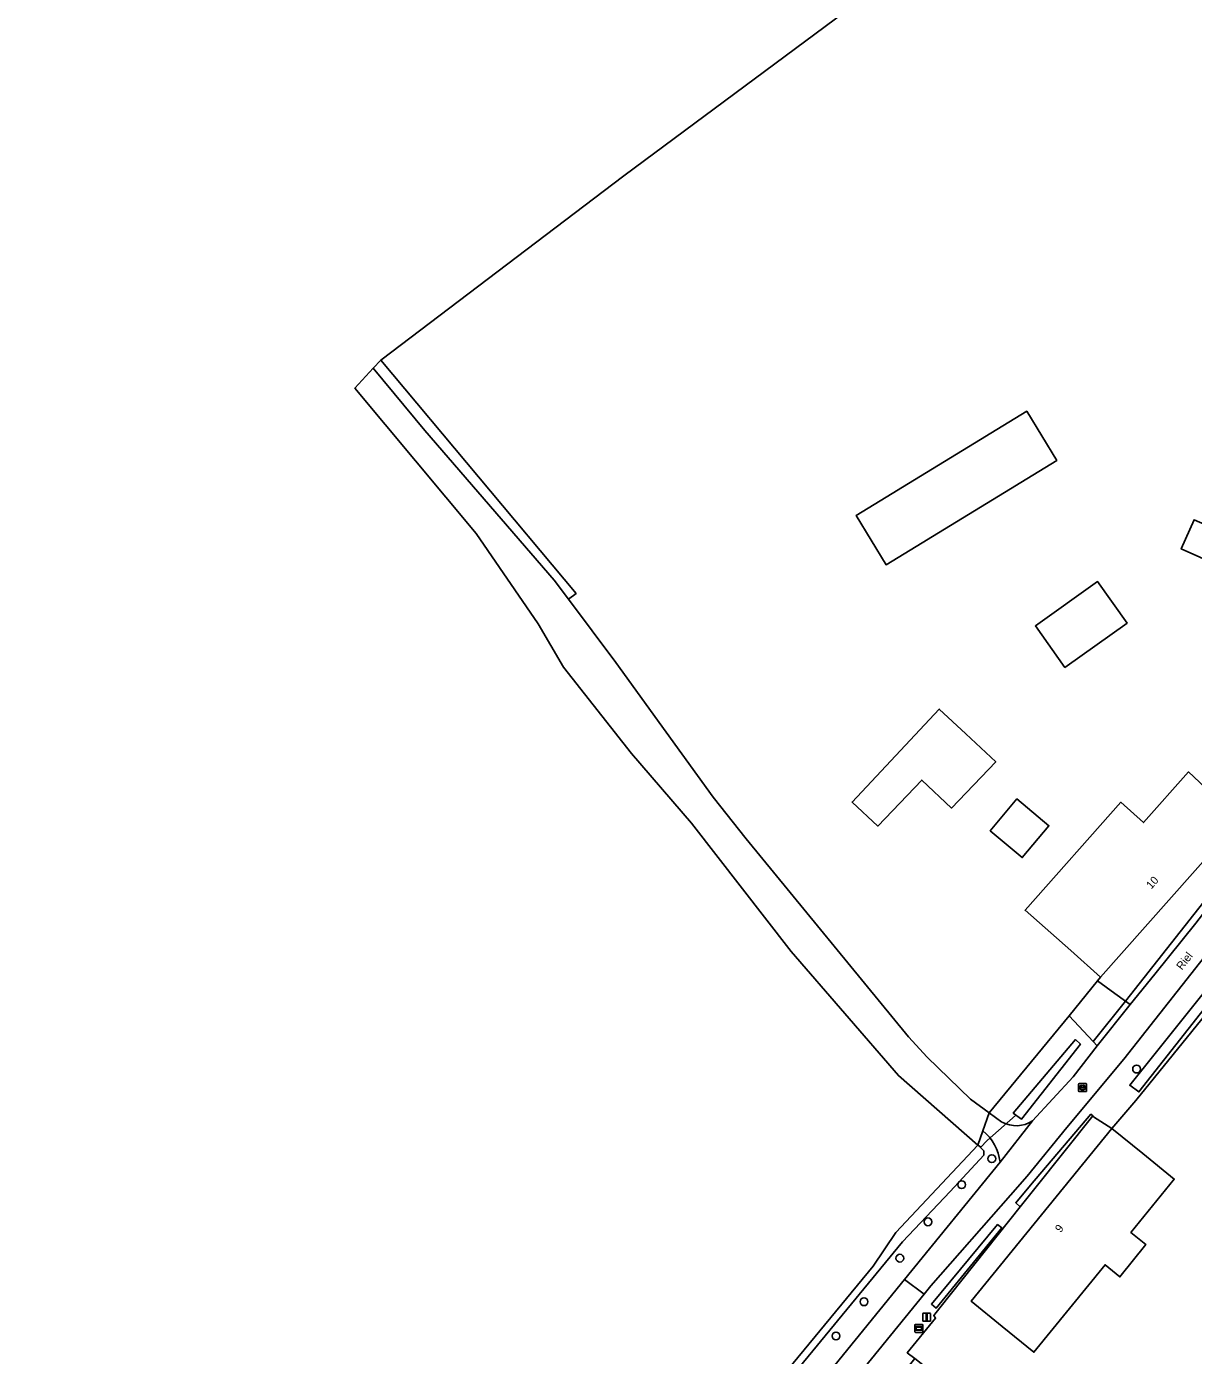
# Model space of a CAD drawing. Extents: x 163859 to 164644, y 379566 to 382155.
# Drawn here: x 164243.3 to 164389, y 381172.1 to 381338.2 of the extents above; entities that cross this region are included whole.
import ezdxf

# ---------------------------------------------------------------- set-up
doc = ezdxf.new("R2010")
doc.units = 0
for name, color, linetype in [('IMGEO_Boom', 7, 'Continuous'), ('IMGEO_Bouwland', 7, 'Continuous'), ('IMGEO_Duiker', 7, 'Continuous'), ('IMGEO_Erf', 7, 'Continuous'), ('IMGEO_Grasland_overig', 7, 'Continuous'), ('IMGEO_Groenvoorziening', 7, 'Continuous'), ('IMGEO_Hek', 7, 'Continuous'), ('IMGEO_Lichtmast', 7, 'Continuous'), ('IMGEO_Openbare_ruimte_label', 7, 'Continuous'), ('IMGEO_Pand', 7, 'Continuous'), ('IMGEO_Pand_nummerreeks', 7, 'Continuous'), ('IMGEO_Pand_overbouw', 7, 'Continuous'), ('IMGEO_Rijbaan_lokaal_gesloten', 7, 'Continuous'), ('IMGEO_Rijbaan_lokaal_halfverhard', 7, 'Continuous'), ('IMGEO_Rioolput', 7, 'Continuous'), ('IMGEO_Verklikker', 7, 'Continuous'), ('IMGEO_Voetpad_gesloten', 7, 'Continuous'), ('IMGEO_Voetpad_open', 7, 'Continuous'), ('IMGEO_Waterloop', 7, 'Continuous')]:
    doc.layers.add(name, color=color, linetype=linetype)

msp = doc.modelspace()

# ---------------------------------------------------------------- linework, layer by layer
at = {"layer": 'IMGEO_Boom'}
for centre in [(164381.95, 381207.91), (164363.86, 381196.71), (164360.09, 381193.46), (164355.88, 381188.82), (164352.37, 381184.28), (164347.89, 381178.84), (164344.39, 381174.56)]:
    msp.add_circle(centre, 0.489, dxfattribs=at)
at = {"layer": 'IMGEO_Bouwland'}
msp.add_lwpolyline([(164187.9, 381189.23), (164278.22, 381095.19), (164281.5, 381099.85), (164286.83, 381106.67), (164289.04, 381110.56), (164349.03, 381183.28), (164351.85, 381187.47), (164362.1, 381198.39), (164352.18, 381207.09), (164338.77, 381222.6), (164326.32, 381238.65), (164318.83, 381247.33), (164310.33, 381258.14), (164307.18, 381263.52), (164299.42, 381274.81), (164284.28, 381292.99), (164286.58, 381295.47), (164287.52, 381296.47), (164317.88, 381319.5), (164350.6, 381343.85)], dxfattribs=at)
at = {"layer": 'IMGEO_Duiker'}
msp.add_lwpolyline([(164362.45, 381198.09), (164363.27, 381198.97), (164366.81, 381202.09)], dxfattribs=at)
at = {"layer": 'IMGEO_Erf'}
msp.add_lwpolyline([(164350.6, 381343.85), (164317.88, 381319.5), (164287.52, 381296.47), (164311.91, 381267.33), (164310.95, 381266.61), (164316.87, 381258.7), (164323.16, 381250), (164329.04, 381241.88), (164333.15, 381236.67), (164353.46, 381211.92), (164355.77, 381209.41), (164361.21, 381204.13), (164363.54, 381202.45), (164373.51, 381214.58), (164377.08, 381218.93), (164377.46, 381219.39), (164373.72, 381222.71), (164368.02, 381227.76), (164379.96, 381241.24), (164382.83, 381238.7), (164388.45, 381245.03), (164391.21, 381242.44)], dxfattribs=at)
for points in [[(164350.64, 381270.92), (164346.89, 381277.06), (164368.23, 381290.1), (164371.98, 381283.96)], [(164377.07, 381268.82), (164380.77, 381263.63), (164373, 381258.09), (164369.3, 381263.28)], [(164360.62, 381249.78), (164364.35, 381246.28), (164358.84, 381240.52), (164355.11, 381244.02), (164349.6, 381238.26), (164346.39, 381241.26), (164357.3, 381252.89)], [(164370.99, 381238.31), (164367.66, 381234.34), (164363.67, 381237.69), (164367, 381241.66)], [(164458.6, 381206.61), (164452.32, 381209.05), (164442.73, 381196.98), (164413.91, 381220.59), (164411.58, 381223.53), (164405.79, 381228.47), (164403.37, 381230.53), (164381.86, 381203.99), (164378.85, 381200.5), (164376.58, 381201.96), (164376.48, 381202.06), (164369.24, 381192.97), (164367.41, 381190.7), (164357.36, 381178.07), (164356.6, 381177.11), (164356.84, 381176.79), (164353.3, 381172.46), (164354.22, 381171.73), (164404.86, 381131.61), (164431.84, 381169.01), (164446.23, 381186.49), (164447.34, 381188.47), (164448.06, 381190.36)], [(164378.85, 381200.5), (164382.73, 381197.35), (164386.65, 381194.16), (164381.23, 381187.51), (164383.12, 381185.97), (164379.86, 381181.95), (164378.01, 381183.46), (164369.12, 381172.53), (164365.17, 381175.74), (164361.29, 381178.9)]]:
    msp.add_lwpolyline(points, close=True, dxfattribs=at)
at = {"layer": 'IMGEO_Grasland_overig'}
for points in [[(164287.52, 381296.47), (164286.58, 381295.47), (164293.02, 381287.69), (164309.18, 381268.98), (164310.95, 381266.61), (164311.91, 381267.33)], [(164286.58, 381295.47), (164284.28, 381292.99), (164299.42, 381274.81), (164307.18, 381263.52), (164310.33, 381258.14), (164318.83, 381247.33), (164326.32, 381238.65), (164338.77, 381222.6), (164352.18, 381207.09), (164362.1, 381198.39), (164362.74, 381200.21), (164363.54, 381202.45), (164361.21, 381204.13), (164355.77, 381209.41), (164353.46, 381211.92), (164333.15, 381236.67), (164329.04, 381241.88), (164323.16, 381250), (164316.87, 381258.7), (164310.95, 381266.61), (164309.18, 381268.98), (164293.02, 381287.69)], [(164366.54, 381202.41), (164374.33, 381211.6), (164374.92, 381211.01), (164367.57, 381201.67)]]:
    msp.add_lwpolyline(points, close=True, dxfattribs=at)
for points in [[(164411.34, 381270.45), (164410.69, 381270.73), (164407.78, 381264.26), (164397.4, 381243.03), (164394.86, 381239.02), (164377.46, 381219.39), (164377.08, 381218.93), (164379.21, 381217.37), (164380.55, 381216.38), (164396.56, 381236.69), (164397.1, 381236.21), (164401.21, 381241.55), (164406.39, 381250), (164407.38, 381251.61)], [(164368.94, 381201.43), (164374.03, 381206.95), (164377.04, 381210.81), (164376.54, 381211.34), (164373.51, 381214.58), (164363.54, 381202.45), (164365.13, 381201.29)]]:
    msp.add_lwpolyline(points, dxfattribs=at)
msp.add_arc((164366.92, 381204.52), 3.69, 241.068, 303.2332, dxfattribs=at)
at = {"layer": 'IMGEO_Groenvoorziening'}
for points in [[(164431.96, 381299.66), (164429.94, 381295.69), (164428.15, 381292.04), (164426.2, 381287.59), (164423.08, 381279.48), (164417.3, 381265.29), (164413.63, 381256.97), (164407.49, 381245.09), (164401.6, 381236.08), (164380.37, 381209.13), (164373.24, 381200.61), (164368.28, 381194.51), (164366.18, 381192.15), (164356.26, 381180.83), (164355.42, 381179.8), (164327.62, 381145.68), (164299.26, 381110.37), (164285.34, 381092.57), (164271.16, 381074.14), (164257.14, 381055.39), (164248.19, 381042.64), (164246.03, 381039.89)], [(164351.1, 381167.85), (164354.22, 381171.73), (164353.3, 381172.46), (164356.84, 381176.79), (164356.6, 381177.11), (164357.36, 381178.07), (164367.41, 381190.7), (164366.86, 381191.21), (164368.7, 381193.39), (164376.24, 381202.26), (164376.48, 381202.06), (164376.58, 381201.96), (164378.85, 381200.5), (164381.86, 381203.99), (164403.37, 381230.53), (164409.33, 381239.2), (164409.26, 381239.26)], [(164362.74, 381200.21), (164362.1, 381198.39), (164362.45, 381198.19), (164362.45, 381198.09), (164362.88, 381197.68), (164362.88, 381197.17), (164358.66, 381192.61), (164352.68, 381186.34), (164315.21, 381140.78), (164290.33, 381110.01), (164284.87, 381100.39), (164279.89, 381093.78), (164279.12, 381094.43), (164278.22, 381095.19), (164276.13, 381091.25), (164277.51, 381089.86), (164260.42, 381068.3), (164239.55, 381038.87), (164238.07, 381040.68), (164237.86, 381040.39), (164240.37, 381037.27)], [(164325.21, 381147.51), (164352.96, 381181.62), (164364.89, 381196.29)]]:
    msp.add_lwpolyline(points, dxfattribs=at)
for points in [[(164381.09, 381205.89), (164402.81, 381233.02), (164403.79, 381232.48), (164382.23, 381205.05)], [(164356.32, 381178.54), (164364.57, 381188.47), (164365.11, 381188.09), (164356.92, 381178.05)]]:
    msp.add_lwpolyline(points, close=True, dxfattribs=at)
msp.add_arc((164358.9, 381195.56), 6.03, 6.9415, 50.4634, dxfattribs=at)
at = {"layer": 'IMGEO_Hek'}
msp.add_lwpolyline([(164387.17, 381367.35), (164350.6, 381343.85), (164317.88, 381319.5), (164287.52, 381296.47), (164311.91, 381267.33)], dxfattribs=at)
at = {"layer": 'IMGEO_Lichtmast'}
for p, q in [((164355.22, 381176.5), (164355.22, 381177.3)), ((164355.22, 381177.3), (164355.22, 381176.5)), ((164355.32, 381177.4), (164356.11, 381177.4)), ((164356.11, 381177.4), (164355.32, 381177.4)), ((164356.11, 381176.4), (164355.32, 381176.4)), ((164355.32, 381176.4), (164356.11, 381176.4)), ((164356.21, 381177.3), (164356.21, 381176.5)), ((164356.21, 381176.5), (164356.21, 381177.3))]:
    msp.add_line(p, q, dxfattribs=at)
msp.add_lwpolyline([(164355.64, 381177.28), (164355.79, 381177.28), (164355.79, 381176.53), (164355.64, 381176.53), (164355.64, 381177.28)], dxfattribs=at)
for centre, start, end in [((164355.32, 381177.3), 90, 180), ((164355.32, 381177.3), 90, 180), ((164355.32, 381176.5), 180, 270), ((164355.32, 381176.5), 180, 270), ((164356.11, 381177.3), 0, 90), ((164356.11, 381177.3), 360, 90), ((164356.11, 381176.5), 270, 0), ((164356.11, 381176.5), 270, 0)]:
    msp.add_arc(centre, 0.1, start, end, dxfattribs=at)
at = {"layer": 'IMGEO_Pand'}
for points in [[(164346.89, 381277.06), (164350.64, 381270.92), (164371.98, 381283.96), (164368.23, 381290.1)], [(164369.3, 381263.28), (164373, 381258.09), (164380.77, 381263.63), (164377.07, 381268.82)], [(164346.39, 381241.26), (164349.6, 381238.26), (164355.11, 381244.02), (164358.84, 381240.52), (164364.35, 381246.28), (164360.62, 381249.78), (164357.3, 381252.89)], [(164377.46, 381219.39), (164394.86, 381239.02), (164391.21, 381242.44), (164388.45, 381245.03), (164382.83, 381238.7), (164379.96, 381241.24), (164368.02, 381227.76), (164373.72, 381222.71)], [(164363.67, 381237.69), (164367.66, 381234.34), (164370.99, 381238.31), (164367, 381241.66)], [(164383.12, 381185.97), (164381.23, 381187.51), (164386.65, 381194.16), (164382.73, 381197.35), (164378.85, 381200.5), (164361.29, 381178.9), (164365.17, 381175.74), (164369.12, 381172.53), (164378.01, 381183.46), (164379.86, 381181.95)]]:
    msp.add_lwpolyline(points, close=True, dxfattribs=at)
at = {"layer": 'IMGEO_Pand_overbouw'}
msp.add_lwpolyline([(164393.81, 381274.5), (164389.13, 381276.55), (164387.52, 381272.89), (164392.2, 381270.84)], close=True, dxfattribs=at)
at = {"layer": 'IMGEO_Rijbaan_lokaal_gesloten'}
for points in [[(164389.34, 381226.14), (164384.21, 381219.76), (164381.13, 381215.96), (164377.04, 381210.81), (164374.03, 381206.95), (164368.94, 381201.43), (164364.89, 381196.29), (164352.96, 381181.62), (164355.42, 381179.8), (164356.26, 381180.83), (164366.18, 381192.15), (164368.28, 381194.51), (164373.24, 381200.61), (164380.37, 381209.13), (164401.6, 381236.08)], [(164271.16, 381074.14), (164285.34, 381092.57), (164299.26, 381110.37), (164327.62, 381145.68), (164355.42, 381179.8), (164352.96, 381181.62), (164325.21, 381147.51), (164297.15, 381112.5), (164283.09, 381094.56), (164268.85, 381076.08), (164254.82, 381057.26), (164245.63, 381044.28)]]:
    msp.add_lwpolyline(points, dxfattribs=at)
at = {"layer": 'IMGEO_Rijbaan_lokaal_halfverhard'}
for points in [[(164365.13, 381201.29), (164363.54, 381202.45), (164362.74, 381200.21)], [(164364.89, 381196.29), (164368.94, 381201.43)]]:
    msp.add_lwpolyline(points, dxfattribs=at)
for centre, radius, start, end in [((164366.92, 381204.52), 3.69, 241.068, 303.2332), ((164358.9, 381195.56), 6.03, 6.9415, 50.4634)]:
    msp.add_arc(centre, radius, start, end, dxfattribs=at)
at = {"layer": 'IMGEO_Rioolput'}
for p, q in [((164374.69, 381205.18), (164374.69, 381206.03)), ((164374.77, 381206.1), (164375.62, 381206.1)), ((164375.62, 381205.1), (164374.77, 381205.1)), ((164374.95, 381205.6), (164374.95, 381205.61)), ((164375.39, 381205.56), (164374.99, 381205.56)), ((164375, 381205.65), (164375.39, 381205.65)), ((164375.18, 381205.88), (164375.21, 381205.88)), ((164375.2, 381205.32), (164375.18, 381205.32)), ((164375.44, 381205.61), (164375.44, 381205.6)), ((164375.7, 381206.03), (164375.7, 381205.18))]:
    msp.add_line(p, q, dxfattribs=at)
for points in [[(164374.69, 381205.18), (164374.69, 381206.03)], [(164374.77, 381206.1), (164375.62, 381206.1)], [(164375.62, 381205.1), (164374.77, 381205.1)], [(164375.7, 381206.03), (164375.7, 381205.18)]]:
    msp.add_lwpolyline(points, dxfattribs=at)
for centre, radius, start, end in [((164374.77, 381206.03), 0.0765, 91.552, 178.448), ((164374.77, 381206.03), 0.0765, 91.552, 178.448), ((164374.77, 381205.18), 0.0765, 181.552, 268.448), ((164374.77, 381205.18), 0.0765, 181.552, 268.448), ((164374.99, 381205.61), 0.0403, 85.8775, 175.7526), ((164374.99, 381205.6), 0.0366, 178.938, 274.7102), ((164375.4, 381205.61), 0.0386, 1.7309, 96.639), ((164375.39, 381205.6), 0.043, 264.8664, 352.4533), ((164375.62, 381206.03), 0.0765, 1.552, 88.448), ((164375.62, 381206.03), 0.0765, 1.552, 88.448), ((164375.62, 381205.18), 0.0765, 271.552, 358.448), ((164375.62, 381205.18), 0.0765, 271.552, 358.448)]:
    msp.add_arc(centre, radius, start, end, dxfattribs=at)
for centre, major_axis, ratio, start_param, end_param in [((164375.18, 381205.6), (-0.387, 0.002), 0.722429, 4.712389, 7.853982), ((164375.21, 381205.6), (-0.39, 0.002), 0.717154, 1.570796, 4.712389)]:
    msp.add_ellipse(centre, major_axis=major_axis, ratio=ratio, start_param=start_param, end_param=end_param, dxfattribs=at)
at = {"layer": 'IMGEO_Verklikker'}
for p, q in [((164354.24, 381175.11), (164354.24, 381175.91)), ((164354.24, 381175.91), (164354.24, 381175.11)), ((164354.34, 381176.01), (164355.13, 381176.01)), ((164355.13, 381176.01), (164354.34, 381176.01)), ((164355.13, 381175.01), (164354.34, 381175.01)), ((164354.34, 381175.01), (164355.13, 381175.01)), ((164355.23, 381175.91), (164355.23, 381175.11)), ((164355.23, 381175.11), (164355.23, 381175.91))]:
    msp.add_line(p, q, dxfattribs=at)
for points in [[(164354.34, 381175.74), (164355.13, 381175.74), (164355.13, 381175.28), (164354.34, 381175.28), (164354.34, 381175.74)], [(164354.41, 381175.68), (164354.41, 381175.34), (164355.06, 381175.34), (164355.06, 381175.68), (164354.41, 381175.68)]]:
    msp.add_lwpolyline(points, dxfattribs=at)
for centre, start, end in [((164354.34, 381175.91), 90, 180), ((164354.34, 381175.91), 90, 180), ((164354.34, 381175.11), 180, 270), ((164354.34, 381175.11), 180, 270), ((164355.13, 381175.91), 0, 90), ((164355.13, 381175.91), 360, 90), ((164355.13, 381175.11), 270, 0), ((164355.13, 381175.11), 270, 0)]:
    msp.add_arc(centre, 0.1, start, end, dxfattribs=at)
at = {"layer": 'IMGEO_Voetpad_gesloten'}
msp.add_lwpolyline([(164380.55, 381216.38), (164379.21, 381217.37), (164377.08, 381218.93), (164373.51, 381214.58), (164376.54, 381211.34)], close=True, dxfattribs=at)
at = {"layer": 'IMGEO_Voetpad_open'}
for points in [[(164389.34, 381226.14), (164397.1, 381236.21), (164396.56, 381236.69), (164380.55, 381216.38), (164381.13, 381215.96), (164384.21, 381219.76)], [(164381.13, 381215.96), (164380.55, 381216.38), (164376.54, 381211.34), (164377.04, 381210.81)]]:
    msp.add_lwpolyline(points, close=True, dxfattribs=at)
at = {"layer": 'IMGEO_Waterloop'}
for points in [[(164382.23, 381205.05), (164403.79, 381232.48), (164402.81, 381233.02), (164381.09, 381205.89)], [(164367.57, 381201.67), (164374.92, 381211.01), (164374.33, 381211.6), (164366.54, 381202.41)], [(164367.41, 381190.7), (164369.24, 381192.97), (164376.48, 381202.06), (164376.24, 381202.26), (164368.7, 381193.39), (164366.86, 381191.21)], [(164362.45, 381198.19), (164362.1, 381198.39), (164351.85, 381187.47), (164349.03, 381183.28), (164289.04, 381110.56), (164286.83, 381106.67), (164281.5, 381099.85), (164278.22, 381095.19), (164279.12, 381094.43), (164279.89, 381093.78), (164284.87, 381100.39), (164290.33, 381110.01), (164315.21, 381140.78), (164352.68, 381186.34), (164358.66, 381192.61), (164362.88, 381197.17), (164362.88, 381197.68), (164362.45, 381198.09)], [(164365.11, 381188.09), (164364.57, 381188.47), (164356.32, 381178.54), (164356.92, 381178.05)]]:
    msp.add_lwpolyline(points, close=True, dxfattribs=at)

# ---------------------------------------------------------------- texts
at = {"layer": 'IMGEO_Openbare_ruimte_label'}
msp.add_text('Riel', height=1, rotation=52.0295, dxfattribs=at).set_placement((164387.61, 381220.21))
at = {"layer": 'IMGEO_Pand_nummerreeks'}
for s, rotation, p in [('10', 48.4416, (164383.79, 381230.33)), ('9', 50.8901, (164372.44, 381187.41))]:
    msp.add_text(s, height=1, rotation=rotation, dxfattribs=at).set_placement(p)

doc.saveas('drawing.dxf')
